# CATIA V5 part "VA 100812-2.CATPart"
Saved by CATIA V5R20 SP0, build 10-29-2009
Part number: VA 100812-2
Revision: ANY
Definition: UNKNOWN
Nomenclature: VA 100812-2
Source: Unknown
Bounding box of the stored display mesh (mm): x -5 to 5, y 0 to 12, z -5 to 5
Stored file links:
  C:\Users\Utente\Desktop\IO LAVORO\3D X SITO CF\CUMSA\3D files VA\VA 100812\VA 100812-2.CATPart
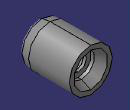
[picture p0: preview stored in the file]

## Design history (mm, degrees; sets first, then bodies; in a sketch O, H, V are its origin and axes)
Body1 "Redondeo1" (main body)
  Solid1: solid without history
